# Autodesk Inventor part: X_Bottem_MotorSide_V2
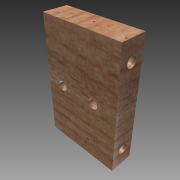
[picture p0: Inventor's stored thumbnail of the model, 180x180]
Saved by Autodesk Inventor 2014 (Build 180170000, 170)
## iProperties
Created: 2013-12
Part Number: X_Bottem_MotorSide_V2
Material: Birch
Document SubType Name: Modeling
Designer: Bram
Density: 0.512 g/cm^3
Appearance: Birch - Natural Medium Gloss
Author: Bram
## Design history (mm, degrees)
sketch "Sketch1"
  geometry: L1 (0, 0)-(60, 0); L2 (60, 0)-(60, 100); L3 (60, 100)-(0, 100); L4 (0, 100)-(0, 0); C1 r 4 at (15, 50); C2 r 4 at (45, 50)
  constraints: 8 end point, 2 centre point, 2 parallel, 1 horizontal, 1 perpendicular
  dimensions: "d0" = 60 distance of L3.end L2.end; "d1" = 100 distance of L2.end L1.end; "d4" = 8 diameter of C1; "d5" = 8 diameter of C2
extrude "Extrusion1" new body sketch "Sketch1" distance "d6" = 20; taper "d7" = 0 deg
sketch "Sketch2"
  geometry: L1 (0, 20)-(100, 20) reference; L2 (0, 0)-(0, 20) reference; L3 (50, 20)-(50, 10); L4 (50, 10)-(85, 10); L5 (50, 10)-(15, 10); C1 r 4 at (15, 10); C2 r 4 at (85, 10)
  constraints: 6 end point, 2 centre point, 2 coincident, 1 collinear, 1 midpoint, 1 parallel, 1 perpendicular
  dimensions: "d8" = 35 distance of L3.end L4.end; "d9" = 35 distance of L3.end L5.end; "d10" = 8 diameter of C1; "d11" = 8 diameter of C2
extrude "Extrusion2" cut sketch "Sketch2" distance "d12" = 80; taper "d13" = 0 deg
sketch "Sketch3"
  geometry: L1 (0, 0)-(100, 0) reference; L2 (100, 0)-(100, 20) reference; L3 (0, 20)-(100, 20) reference; L4 (0, 0)-(0, 20) reference; C1 r 4 at (15, 10) reference; C2 r 4 at (85, 10) reference
extrude "Extrusion3" join sketch "Sketch3" distance "d14" = 5; taper "d15" = 0 deg
body "Solid1"
